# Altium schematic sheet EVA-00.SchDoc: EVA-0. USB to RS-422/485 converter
size A4; Engineer: Strannik
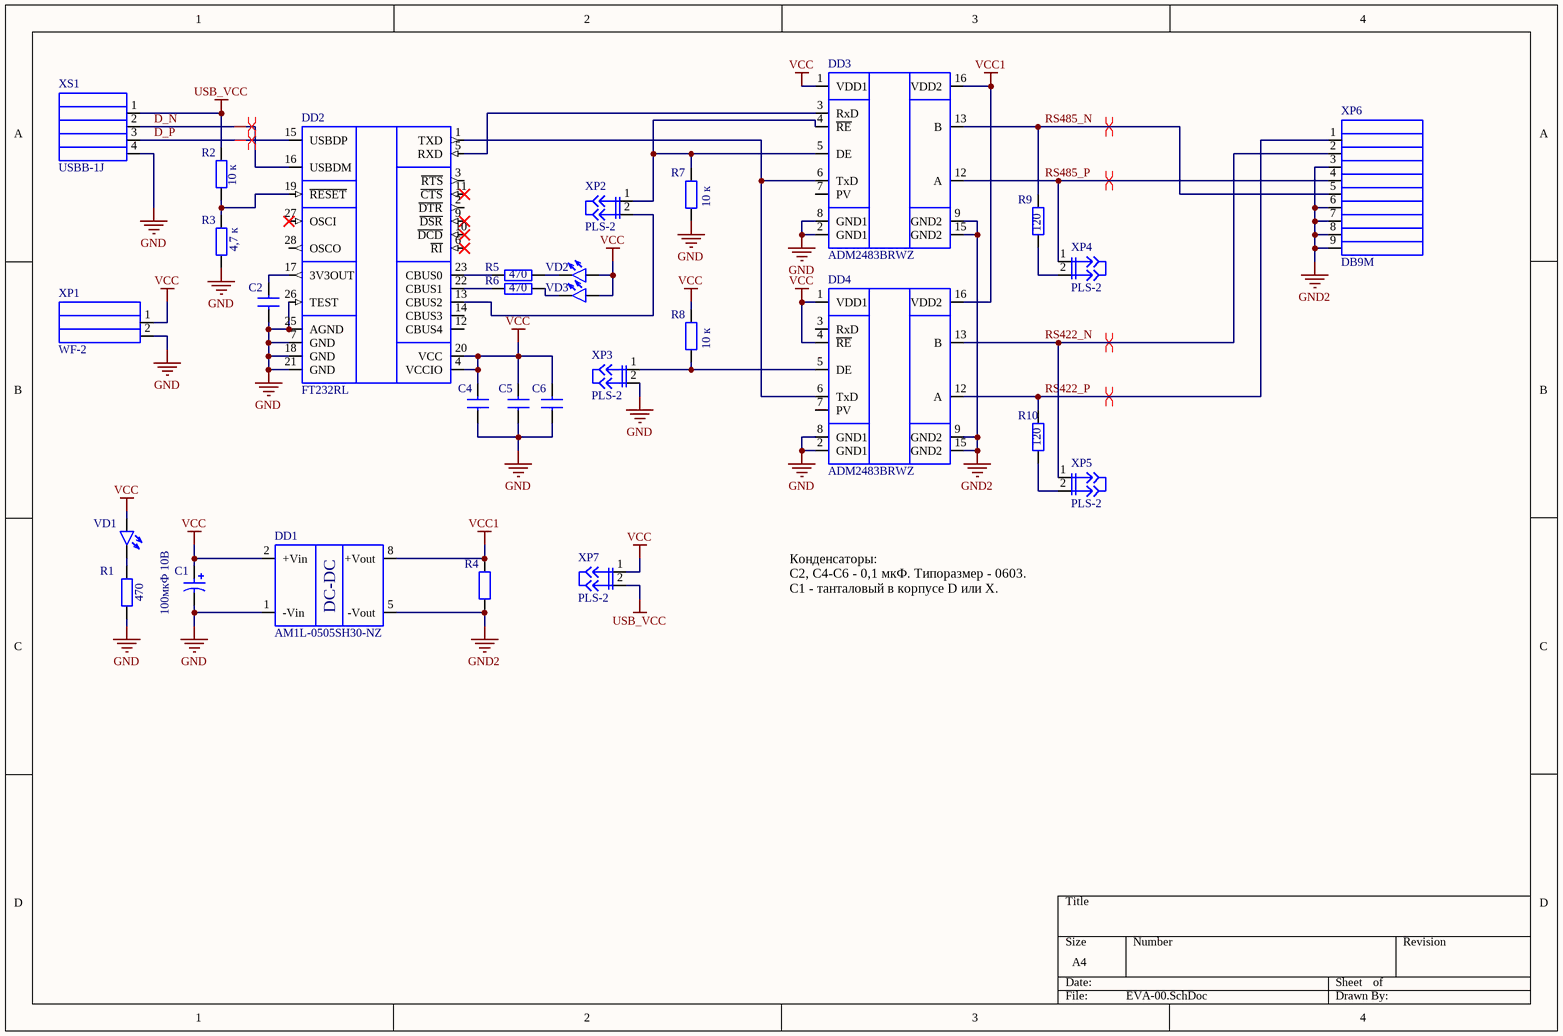
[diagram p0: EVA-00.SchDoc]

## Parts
C1  value 100мкФ 10В  [X-7343-43]  (hidden comment: Танталовый ЧИП конденсатор 220мкФ х 10В тип X)
C2  C <0603> 0,1 мкФ±20% 25В  [0603]  (value not drawn)
C4  C <0603> 0,1 мкФ±20% 25В  [0603]  (value not drawn)
C5  C <0603> 0,1 мкФ±20% 25В  [0603]  (value not drawn)
C6  C <0603> 0,1 мкФ±20% 25В  [0603]  (value not drawn)
DD1  AM1L-0505SH30-NZ  [SMD12]
DD2  FT232RL  [SSOP-28 (MO-150-AH)]
DD3  ADM2483BRWZ  [SOIC-16 (MS-013-AA)]
DD4  ADM2483BRWZ  [SOIC-16 (MS-013-AA)]
R1  value 470  [0603]  (hidden comment: R0603-470 Ом-5%)
R2  value 4,7 к  [0603]  (hidden comment: R0603-4,7кОм-5%)
R3  value 10 к  [0603]  (hidden comment: R0603-10кОм-5%)
R4  R0603-240 Ом-5%  [0603]  (value not drawn)
R5  value 470  [0603]  (hidden comment: R0603-470 Ом-5%)
R6  value 470  [0603]  (hidden comment: R0603-470 Ом-5%)
R7  value 10 к  [0603]  (hidden comment: R0603-10кОм-5%)
R8  value 10 к  [0603]  (hidden comment: R0603-10кОм-5%)
R9  value 120  [0603]  (hidden comment: R0603-120 Ом-5%)
R10  value 120  [0603]  (hidden comment: R0603-120 Ом-5%)
VD1  LED_d3mm  [LED_d3mm]  (value not drawn)
VD2  LED_d3mm  [LED_d3mm]  (value not drawn)
VD3  LED_d3mm  [LED_d3mm]  (value not drawn)
XP1  WF-2  [WF-2]
XP2  PLS-2  [PLS-2]
XP3  PLS-2  [PLS-2]
XP4  PLS-2  [PLS-2]
XP5  PLS-2  [PLS-2]
XP6  DB9M  [DB9M]
XP7  PLS-2  [PLS-2]
XS1  USBB-1J  [USBB-1J]

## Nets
GND: C1.2 C2.1 C4.1 C5.1 C6.1 DD1.1(-Vin) DD2.7(GND) DD2.18(GND) DD2.21(GND) DD2.25(AGND) DD2.26(TEST) DD3.2(GND1) DD3.8(GND1) DD4.2(GND1) DD4.8(GND1) R1.1 R3.1 R7.1 XP1.2 XP3.2 XS1.4
GND2: DD1.5(-Vout) DD3.9(GND2) DD3.15(GND2) DD4.9(GND2) DD4.15(GND2) R4.1 XP6.3 XP6.6 XP6.7 XP6.8 XP6.9
USB_VCC: R2.2 XP7.2 XS1.1
VCC: C1.1 C4.2 C5.2 C6.2 DD1.2(+Vin) DD2.4(VCCIO) DD2.20(VCC) DD3.1(VDD1) DD4.1(VDD1) DD4.4(~{RE}) R8.2 VD1.1 VD2.1 VD3.1 XP1.1 XP7.1
VCC1: DD1.8(+Vout) DD3.16(VDD2) DD4.16(VDD2) R4.2
D_N: DD2.16(USBDM) XS1.2
D_P: DD2.15(USBDP) XS1.3
RS422_N: DD4.13(B) XP5.1 XP6.2
RS422_P: DD4.12(A) R10.2 XP6.1
RS485_N: DD3.13(B) R9.2 XP6.5
RS485_P: DD3.12(A) XP4.1 XP6.4
NetC2_2: C2.2 DD2.17(3V3OUT)
NetDD2_1: DD2.1(TXD) DD3.6(TxD) DD4.6(TxD)
NetDD2_5: DD2.5(RXD) DD3.3(RxD)
NetDD2_13: DD2.13(CBUS2) XP2.2
NetDD2_19: DD2.19(~{RESET}) R2.1 R3.2
NetDD2_22: DD2.22(CBUS1) R6.1
NetDD2_23: DD2.23(CBUS0) R5.1
NetDD3_4: DD3.4(~{RE}) DD3.5(DE) R7.2 XP2.1
NetDD4_5: DD4.5(DE) R8.1 XP3.1
NetR1_2: R1.2 VD1.2
NetR5_2: R5.2 VD2.2
NetR6_2: R6.2 VD3.2
NetR9_1: R9.1 XP4.2
NetR10_1: R10.1 XP5.2

Not connected (* = marked no-connect by the designer): DD2 2(~{DTR}) 3(~{RTS}) 6(~{RI})* 8(NC) 9(~{DSR})* 10(~{DCD})* 11(~{CTS})* 12(CBUS4) 14(CBUS3) 24(NC) 27(OSCI)* 28(OSCO); DD3 7(PV) 10(NC) 11(NC) 14(NC); DD4 3(RxD) 7(PV) 10(NC) 11(NC) 14(NC)

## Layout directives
differential pair: D_N, D_P, RS422_N, RS422_P, RS485_N, RS485_P

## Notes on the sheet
- Конденсаторы:
  С2, С4-С6 - 0,1 мкФ. Типоразмер - 0603.
  С1 - танталовый в корпусе D или X.

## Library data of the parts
C1 = Танталовый ЧИП конденсатор 220мкФ х 10В тип X: Конденсатор танталовый, 220мкФ х 10В, тип корпуса D (7343-31)
C2 C4-C6 = C <0603> 0,1 мкФ±20% 25В: Library Reference: C0603-10нФ-5%
DD1 = AM1L-0505SH30-NZ: Series AM1L-NZ 1 Watt | DC-DC Converter
DD2 = FT232RL: USB UART Asynchronous Serial Data Transfer Chip, SSOP-28, Pb-Free
DD3 DD4 = ADM2483BRWZ: Half-Duplex, iCoupler Isolated RS-485 Transceiver
R4 = R0603-240 Ом-5%: Value: 240 Ом
XP1 = WF-2: Разъем питания 2 конт.(п) шаг 2,54 на плату
XP2-XP5 XP7 = PLS-2: PLS-2 вилка штыревая 2.54мм 1x2 прямая
XP6 = DB9M: Name Type Description    D-SUB9 M Footprint Connector; D Subminiature; 9 Position; Right Angle; Pitch 1.385 mm
XS1 = USBB-1J: Разъем USB (м) на плату, тип B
